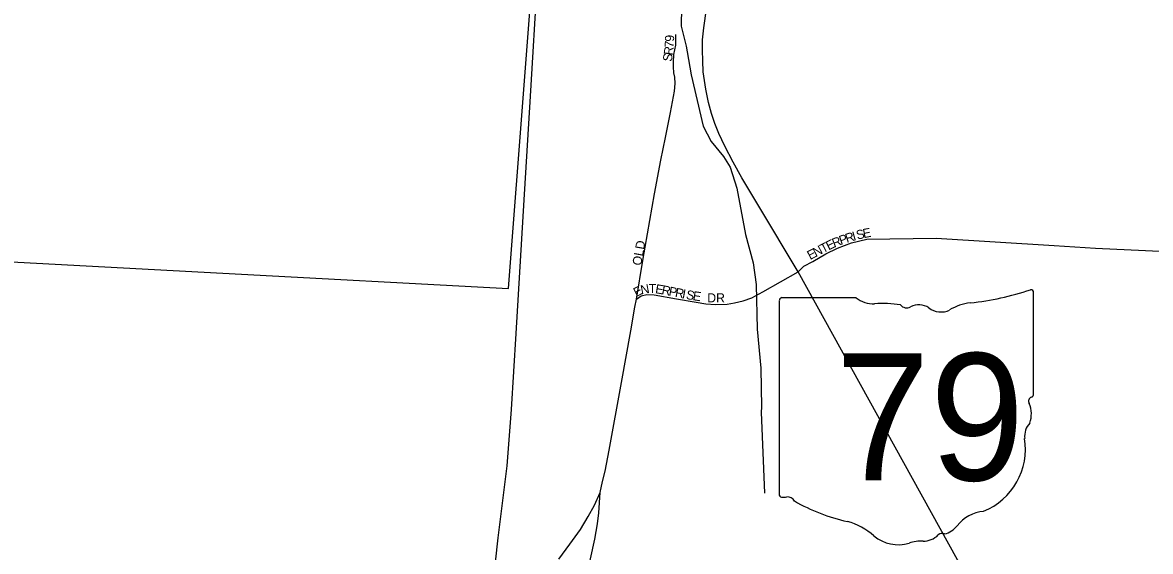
# Model space of a CAD drawing. Extents: x 0 to 40.4, y 0 to 22.
# Drawn here: x 6.04 to 7.209, y 17.403 to 17.952 of the extents above; entities that cross this region are included whole.
import ezdxf

# ---------------------------------------------------------------- set-up
doc = ezdxf.new("R2010")
doc.units = 0
for name, color, linetype in [('GM_X_City_Street', 7, 'Continuous'), ('GM_X_City_Street_Text', 7, 'Continuous'), ('GM_X_Corporation', 7, 'Continuous'), ('GM_X_Minor_River', 7, 'Continuous'), ('GM_X_Rail_Line', 7, 'Continuous'), ('GM_X_State_Route', 7, 'Continuous'), ('GM_X_State_Shield', 7, 'Continuous')]:
    doc.layers.add(name, color=color, linetype=linetype)

msp = doc.modelspace()

# ---------------------------------------------------------------- linework, layer by layer
at = {"layer": 'GM_X_City_Street'}
for points in [[(6.676, 17.6647), (6.6828, 17.7049), (6.6949, 17.7741), (6.7015, 17.8088), (6.7063, 17.8326), (6.7114, 17.8584), (6.7155, 17.8805), (6.7163, 17.8885), (6.7159, 17.8951), (6.715, 17.8995), (6.7145, 17.9056), (6.7145, 17.9107), (6.715, 17.9186), (6.7168, 17.9283), (6.717, 17.9394)], [(7.1092, 17.7203), (7.1519, 17.7177), (7.3742, 17.7074), (7.3858, 17.7093), (7.4054, 17.7165), (7.4358, 17.7443), (7.4931, 17.7982), (7.5243, 17.8294), (7.5409, 17.8499), (7.5422, 17.894), (7.5446, 17.9376)], [(6.8436, 17.6932), (6.8497, 17.6989), (6.8589, 17.7038), (6.8726, 17.7118), (6.8845, 17.7176), (6.8991, 17.7231), (6.9148, 17.7271), (6.9867, 17.728), (7.1092, 17.7203)], [(6.676, 17.6647), (6.681, 17.6681), (6.6869, 17.6697), (6.6944, 17.6693), (6.7175, 17.6652), (6.738, 17.6615), (6.7479, 17.6599), (6.7582, 17.6592), (6.77, 17.6595), (6.7778, 17.6608), (6.7867, 17.6631), (6.7958, 17.6663), (6.807, 17.6724), (6.8436, 17.6932)], [(6.5956, 17.3952), (6.607, 17.4105), (6.6181, 17.4258), (6.6262, 17.4393), (6.6325, 17.451), (6.6385, 17.4644), (6.6408, 17.4756), (6.6435, 17.4864), (6.6479, 17.5081), (6.6605, 17.5782), (6.6704, 17.6318), (6.6743, 17.6565), (6.676, 17.6647)], [(6.5873, 17.2683), (6.5928, 17.2701), (6.5985, 17.2723), (6.6035, 17.2756), (6.6063, 17.2824), (6.609, 17.2908), (6.6149, 17.3224), (6.6223, 17.3633), (6.6243, 17.3729), (6.6285, 17.3955), (6.6328, 17.416), (6.6357, 17.4318), (6.6371, 17.4432), (6.6385, 17.4644)]]:
    msp.add_lwpolyline(points, dxfattribs=at)
at = {"layer": 'GM_X_Corporation'}
msp.add_lwpolyline([(5.9507, 17.7076), (6.5433, 17.6757), (6.5768, 18.1113)], dxfattribs=at)
at = {"layer": 'GM_X_Minor_River'}
msp.add_lwpolyline([(6.7232, 17.9876), (6.7224, 17.9478), (6.7276, 17.927), (6.7287, 17.9213), (6.7328, 17.8974), (6.7452, 17.8443), (6.7535, 17.8283), (6.7663, 17.8128), (6.7731, 17.8018), (6.7802, 17.7798), (6.7892, 17.732), (6.7971, 17.7024), (6.8001, 17.68), (6.8011, 17.6337), (6.8052, 17.5932), (6.8059, 17.5526), (6.8055, 17.5477), (6.8087, 17.4635)], dxfattribs=at)
at = {"layer": 'GM_X_Rail_Line'}
msp.add_lwpolyline([(6.512, 17.2264), (6.5195, 17.2953), (6.5227, 17.3257), (6.5327, 17.4171), (6.5419, 17.4918), (6.5467, 17.5503), (6.5515, 17.629), (6.5597, 17.7679), (6.5658, 17.8694), (6.5737, 18.0027)], dxfattribs=at)
at = {"layer": 'GM_X_State_Route'}
for points in [[(6.7466, 17.9511), (6.7479, 17.9609), (6.7502, 17.9746), (6.7616, 18.02)], [(6.7454, 17.9009), (6.7449, 17.9116), (6.7444, 17.9234), (6.7447, 17.9337), (6.746, 17.9461), (6.7466, 17.9511)], [(6.8436, 17.6932), (6.8436, 17.6932), (6.8031, 17.7613), (6.7855, 17.7905), (6.7762, 17.8068), (6.7677, 17.8236), (6.7616, 17.8365), (6.7575, 17.847), (6.7538, 17.8575), (6.7509, 17.8688), (6.7481, 17.8826), (6.7454, 17.9004), (6.7454, 17.9009)], [(7.1476, 17.1281), (7.1476, 17.1281), (7.1271, 17.1832), (7.0944, 17.2487), (7.0689, 17.2906), (7.0509, 17.3238), (7.0178, 17.378), (6.8436, 17.6932)]]:
    msp.add_lwpolyline(points, dxfattribs=at)
at = {"layer": 'GM_X_State_Shield'}
for p, q in [((7.0878, 17.5666), (7.0878, 17.6712)), ((6.8241, 17.6628), (6.8241, 17.4627)), ((6.9039, 17.6663), (6.8267, 17.6663)), ((7.0878, 17.5666), (7.0878, 17.5666))]:
    msp.add_line(p, q, dxfattribs=at)
for centre, radius, start, end in [((6.9939, 17.9391), 0.2796, 275.8445, 288.9065), ((7.0849, 17.6717), 0.00294, 351.8621, 97.738), ((6.8272, 17.6633), 0.00305, 98.1301, 188.1301), ((6.9223, 17.6895), 0.0296, 231.6195, 271.1119), ((6.9322, 17.5539), 0.1064, 80.4867, 94.9883), ((6.9563, 17.6643), 0.00855, 219.7921, 297.1024), ((6.9689, 17.6412), 0.0178, 54.4667, 119.1411), ((7.0295, 17.6052), 0.0563, 97.3462, 120.7689), ((6.9918, 17.6729), 0.0214, 233.8562, 294.8282), ((7.0847, 17.5662), 0.00314, 289.6038, 7.7341), ((7.0871, 17.5589), 0.00454, 107.944, 210.337), ((7.0582, 17.5456), 0.0273, 340.033, 23.6496), ((7.0983, 17.5227), 0.0198, 136.8065, 186.9296), ((7.0095, 17.5094), 0.0699, 292.3089, 8.9858), ((6.8272, 17.4623), 0.00308, 171.9584, 258.3066), ((6.8276, 17.4828), 0.0235, 267.339, 280.6039), ((6.8325, 17.4512), 0.00848, 29.7484, 93.2717), ((6.9395, 17.631), 0.2019, 240.4129, 257.1985), ((7.039, 17.4065), 0.0383, 94.4031, 142.5768), ((6.8793, 17.3728), 0.0632, 47.1842, 75.836), ((6.9905, 17.4433), 0.0226, 282.8732, 323.2771), ((6.9476, 17.4502), 0.0401, 230.7004, 286.2918), ((6.9708, 17.381), 0.0329, 85.6951, 111.2099), ((6.9737, 17.4352), 0.0214, 268.777, 315.5493), ((6.9931, 17.4158), 0.00601, 65.7517, 132.6484)]:
    msp.add_arc(centre, radius, start, end, dxfattribs=at)

# ---------------------------------------------------------------- texts
at = {"layer": 'GM_X_City_Street_Text'}
for s, rotation, p in [('9', 89.4234, (6.7151, 17.9318)), ('R', 82.3721, (6.7136, 17.9173)), ('7', 85.5864, (6.7146, 17.9253)), ('S', 82.3566, (6.7127, 17.9107)), ('R', 21.585, (6.8811, 17.7181)), ('P', 19.0309, (6.888, 17.7209)), ('R', 17.3135, (6.8942, 17.723)), ('I', 16.0294, (6.9013, 17.7252)), ('S', 14.1887, (6.9052, 17.7264)), ('E', 10.5492, (6.9116, 17.728)), ('OLD', 79.8732, (6.681, 17.6991)), ('E', 27.1759, (6.8561, 17.7053)), ('N', 27.1797, (6.862, 17.7084)), ('T', 27.1759, (6.8695, 17.7122)), ('E', 27.0294, (6.8754, 17.7152)), ('N', 10.6626, (6.6812, 17.6696)), ('T', 359.5355, (6.6889, 17.6711)), ('E', 26.9072, (6.6759, 17.6669)), ('E', 350.0886, (6.6951, 17.6711)), ('R', 349.2998, (6.7017, 17.67)), ('P', 349.1723, (6.709, 17.6686)), ('R', 349.1521, (6.7156, 17.6673)), ('I', 349.1697, (6.7229, 17.6659)), ('S', 349.1454, (6.727, 17.6651)), ('E', 351.5906, (6.734, 17.6638)), ('DR', 0, (6.7495, 17.6614))]:
    msp.add_text(s, height=0.00947, rotation=rotation, dxfattribs=at).set_placement(p)
at = {"layer": 'GM_X_State_Shield'}
msp.add_text('79', height=0.13184, dxfattribs=at).set_placement((6.8823, 17.4768))

doc.saveas('drawing.dxf')
